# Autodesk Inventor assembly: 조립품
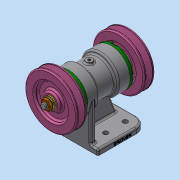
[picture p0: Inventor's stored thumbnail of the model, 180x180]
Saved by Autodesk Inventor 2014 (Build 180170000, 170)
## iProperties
Created: 2020-06
Part Number: 조립품
Document SubType Name: Assembly
Designer: kh
Author: kh
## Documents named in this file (12)
- C:\Users\kh\Desktop\700606V1028\조립품.iam
- C:\Users\kh\Desktop\700606V1028\본체.ipt
- C:\Users\kh\Desktop\700606V1028\축.ipt
- C:\Users\kh\Desktop\700606V1028\베어링 6204.ipt
- C:\Users\kh\Desktop\700606V1028\커버.ipt
- C:\Users\kh\Desktop\700606V1028\오일 실 20 32 5.ipt
- C:\Users\kh\Desktop\700606V1028\키 5x5x12.ipt
- C:\Users\kh\Desktop\700606V1028\V-벨트풀리.ipt
- C:\Users\kh\Desktop\700606V1028\스프링 와셔 10.ipt
- C:\Users\kh\Desktop\700606V1028\평면 와셔 10x21.ipt
- C:\Users\kh\Desktop\700606V1028\너트 M10.ipt
- C:\Users\kh\Desktop\700606V1028\볼트 M4.ipt
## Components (2 placed, 1 different names)
1. V-벨트풀리:1 — Mate:23, Mate:24, Flush:1, Mate:34
2. V-벨트풀리:2 — Mate:25, Mate:26, Flush:2, Mate:28
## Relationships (8: Mate 6, Flush 2)
- Mate:23: V-벨트풀리:1
- Mate:24: V-벨트풀리:1
- Flush:1: V-벨트풀리:1
- Mate:25: V-벨트풀리:2
- Mate:26: V-벨트풀리:2
- Flush:2: V-벨트풀리:2
- Mate:28: V-벨트풀리:2
- Mate:34: V-벨트풀리:1
